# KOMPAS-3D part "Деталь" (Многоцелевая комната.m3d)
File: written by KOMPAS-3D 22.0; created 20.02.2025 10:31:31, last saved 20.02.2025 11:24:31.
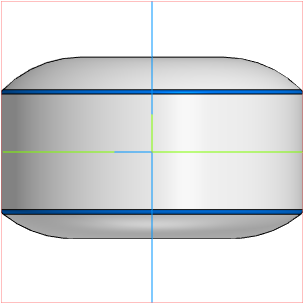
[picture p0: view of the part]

Document properties: Автор: Пользователь Windows; Полное имя файла: C:\Users\Student\Documents\Картошечка\База Сабнатика\Многоцелевая комната\Многоцелевая комната.m3d

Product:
- Part/product: Деталь
    Масса: 0.420426

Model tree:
1. Эскиз:3
2. Элемент вращения:1
     Угол 1 = 360
3. Скругление:1  (with: Элемент вращения:1)
     Радиус = 1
